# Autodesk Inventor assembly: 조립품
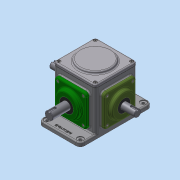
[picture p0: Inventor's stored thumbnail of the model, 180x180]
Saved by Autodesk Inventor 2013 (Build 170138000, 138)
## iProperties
Created: 2019-04
Part Number: 조립품
Document SubType Name: Assembly
Designer: dgall
Author: dgall
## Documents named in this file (16)
- C:\Users\dgall\Desktop\390407V1025\조립품.iam
- C:\Users\dgall\Desktop\390407V1025\본체.ipt
- C:\Users\dgall\Desktop\390407V1025\개스킷.ipt
- C:\Users\dgall\Desktop\390407V1025\메인베벨기어.ipt
- C:\Users\dgall\Desktop\390407V1025\메인축.ipt
- C:\Users\dgall\Desktop\390407V1025\메인커버.ipt
- C:\Users\dgall\Desktop\390407V1025\베어링 6204.ipt
- C:\Users\dgall\Desktop\390407V1025\상부커버.ipt
- C:\Users\dgall\Desktop\390407V1025\오일 실 20 35 8.ipt
- C:\Users\dgall\Desktop\390407V1025\베어링 6203.ipt
- C:\Users\dgall\Desktop\390407V1025\서브베벨기어.ipt
- C:\Users\dgall\Desktop\390407V1025\서브축.ipt
- C:\Users\dgall\Desktop\390407V1025\서브커버.ipt
- C:\Users\dgall\Desktop\390407V1025\오일 실 17 32 8.ipt
- C:\Users\dgall\Desktop\390407V1025\키 4x4.ipt
- C:\Users\dgall\Desktop\390407V1025\볼트 M4.ipt
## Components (1 placed, 1 different names)
1. 개스킷:1
